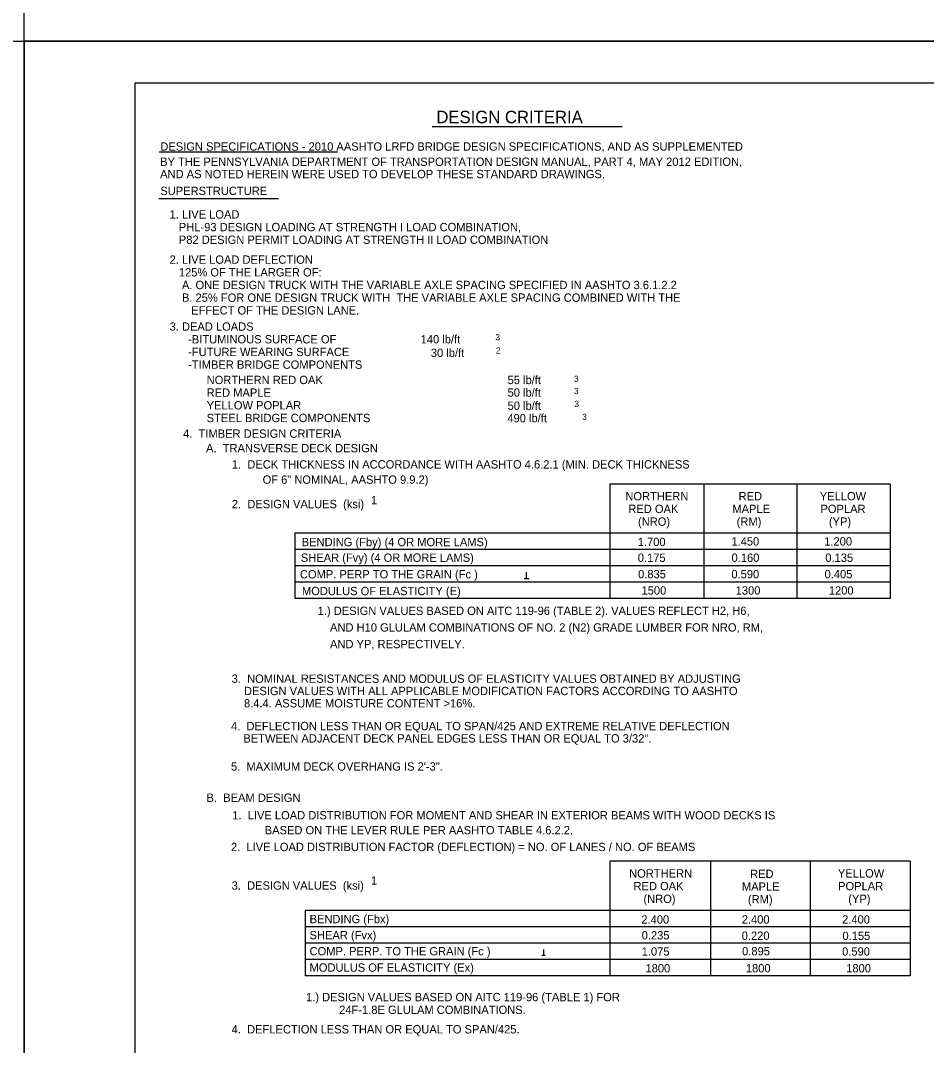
# Model space of a CAD drawing. Extents: x 637594 to 640253, y 297247 to 298435.
# Drawn here: x 639275.1 to 639602, y 297479.2 to 297849 of the extents above; entities that cross this region are included whole.
import ezdxf

# ---------------------------------------------------------------- set-up
doc = ezdxf.new("R2010")
doc.units = 0
for name, color, linetype in [('2', 7, 'Continuous'), ('53', 7, 'Continuous'), ('Level 2', 7, 'Continuous'), ('Level 53', 7, 'Continuous'), ('PLT-BNDY', 7, 'Continuous')]:
    doc.layers.add(name, color=color, linetype=linetype)

msp = doc.modelspace()

# ---------------------------------------------------------------- linework, layer by layer
at = {"layer": '2'}
for p, q in [((639316.46, 297262.46), (639316.46, 297826.46)), ((639316.46, 297826.46), (640102.46, 297826.46))]:
    msp.add_line(p, q, dxfattribs=at)
at = {"layer": '53'}
msp.add_line((639423.58, 297810.75), (639492.23, 297810.75), dxfattribs=at)
at = {"layer": 'Level 2'}
for p, q in [((639588.92, 297681.72), (639487.78, 297681.72)), ((639487.78, 297681.72), (639487.78, 297640.41)), ((639521.66, 297681.72), (639521.66, 297640.41)), ((639555.26, 297681.72), (639555.26, 297640.41)), ((639588.92, 297681.72), (639588.92, 297640.41)), ((639374.08, 297664.01), (639374.08, 297640.41)), ((639487.78, 297664.01), (639374.08, 297664.01)), ((639588.92, 297664.01), (639487.78, 297664.01)), ((639487.78, 297658.11), (639374.08, 297658.11)), ((639588.92, 297658.11), (639487.78, 297658.11)), ((639487.78, 297652.21), (639374.08, 297652.21)), ((639588.92, 297652.21), (639487.78, 297652.21)), ((639457.65, 297647.72), (639457.65, 297649.98)), ((639487.78, 297646.31), (639374.08, 297646.31)), ((639456.83, 297647.72), (639458.48, 297647.72)), ((639588.92, 297646.31), (639487.78, 297646.31)), ((639487.78, 297640.41), (639374.08, 297640.41)), ((639588.92, 297640.41), (639487.78, 297640.41)), ((639596.16, 297545.65), (639487.78, 297545.65)), ((639487.78, 297545.65), (639487.78, 297504.34)), ((639524.02, 297545.65), (639524.02, 297504.34)), ((639560.02, 297545.65), (639560.02, 297504.34)), ((639596.16, 297545.65), (639596.16, 297504.34)), ((639377.82, 297527.95), (639377.82, 297504.34)), ((639487.78, 297527.95), (639377.83, 297527.95)), ((639596.16, 297527.95), (639487.78, 297527.95)), ((639487.78, 297522.05), (639377.83, 297522.05)), ((639596.16, 297522.05), (639487.78, 297522.05)), ((639487.78, 297516.15), (639377.83, 297516.15)), ((639596.16, 297516.15), (639487.78, 297516.15)), ((639463.2, 297511.75), (639464.42, 297511.75)), ((639463.8, 297513.79), (639463.8, 297511.75)), ((639487.78, 297510.24), (639377.83, 297510.24)), ((639596.16, 297510.24), (639487.78, 297510.24)), ((639487.78, 297504.34), (639377.83, 297504.34)), ((639596.16, 297504.34), (639487.78, 297504.34))]:
    msp.add_line(p, q, dxfattribs=at)
at = {"layer": 'Level 53'}
for p, q in [((639325.13, 297801.6), (639389.52, 297801.6)), ((639325.04, 297784.77), (639368.14, 297784.77))]:
    msp.add_line(p, q, dxfattribs=at)
at = {"layer": 'PLT-BNDY'}
for points in [[(639276.46, 298435.46), (640117.46, 298435.46), (640117.46, 297841.46), (639276.46, 297841.46)], [(638435.46, 297841.46), (639276.46, 297841.46), (639276.46, 297247.46), (638435.46, 297247.46)], [(639276.46, 297841.46), (640117.46, 297841.46), (640117.46, 297247.46), (639276.46, 297247.46)]]:
    msp.add_lwpolyline(points, close=True, dxfattribs=at)

# ---------------------------------------------------------------- texts
at = {"layer": '2'}
for s, p in [('3', (639446.45, 297733.56)), ('2', (639446.68, 297728.81)), ('3', (639474.79, 297718.6)), ('3', (639474.79, 297714.17)), ('3', (639474.95, 297709.52)), ('3', (639477.77, 297704.86))]:
    msp.add_text(s, height=2.25, dxfattribs=at).set_placement(p)
at = {"layer": '53'}
msp.add_text('DESIGN CRITERIA', height=4.5002, dxfattribs=at).set_placement((639425.15, 297811.9))
at = {"layer": 'Level 2'}
for s, p in [('55 lb/ft ', (639450.85, 297717.79)), ('50 lb/ft ', (639450.85, 297713.26)), ('50 lb/ft ', (639450.85, 297708.5)), ('490 lb/ft ', (639450.77, 297704.02)), ('4.  TIMBER DESIGN CRITERIA', (639333.78, 297698.43)), ('A.  TRANSVERSE DECK DESIGN', (639342.05, 297693.2)), ('1.  DECK THICKNESS IN ACCORDANCE WITH AASHTO 4.6.2.1 (MIN. DECK THICKNESS', (639351.37, 297687.34)), ('OF 6" NOMINAL, AASHTO 9.9.2)', (639362.46, 297681.84)), ('1', (639401.58, 297674.48)), ('NORTHERN', (639493.34, 297675.86)), ('RED', (639534.19, 297675.86)), ('YELLOW', (639563.49, 297675.86)), ('2.  DESIGN VALUES  (ksi)', (639351.37, 297673.03)), ('RED OAK', (639494.41, 297671.28)), ('MAPLE', (639531.95, 297671.28)), ('POPLAR', (639563.73, 297671.28)), ('(NRO)', (639497.9, 297666.69)), ('(RM)', (639533.51, 297666.69)), ('(YP)', (639566.78, 297666.69)), ('1.450', (639531.6, 297659.57)), ('1.200', (639565.09, 297659.57)), ('BENDING (Fby) (4 OR MORE LAMS)', (639376.57, 297659.33)), ('1.700', (639497.81, 297659.37)), ('SHEAR (Fvy) (4 OR MORE LAMS)', (639376.26, 297653.68)), ('0.175', (639497.82, 297653.66)), ('0.160', (639531.66, 297653.66)), ('0.135', (639565.49, 297653.66)), ('COMP. PERP TO THE GRAIN (Fc )', (639375.92, 297647.7)), ('0.835', (639497.94, 297647.76)), ('0.590', (639531.6, 297647.76)), ('0.405', (639565.22, 297647.76)), ('MODULUS OF ELASTICITY (E)', (639376.65, 297641.66)), ('1500', (639499.18, 297641.86)), ('1300', (639533.15, 297641.86)), ('1200', (639566.76, 297641.86)), ('1.) DESIGN VALUES BASED ON AITC 119-96 (TABLE 2). VALUES REFLECT H2, H6,', (639382.32, 297634.52)), ('    AND H10 GLULAM COMBINATIONS OF NO. 2 (N2) GRADE LUMBER FOR NRO, RM,', (639382.32, 297628.52)), ('    AND YP, RESPECTIVELY.', (639382.32, 297622.52)), ('3.  NOMINAL RESISTANCES AND MODULUS OF ELASTICITY VALUES OBTAINED BY ADJUSTING', (639351.28, 297610.04)), ('    DESIGN VALUES WITH ALL APPLICABLE MODIFICATION FACTORS ACCORDING TO AASHTO', (639351.28, 297605.6)), ('    8.4.4. ASSUME MOISTURE CONTENT >16%. ', (639351.28, 297601.16)), ('4.  DEFLECTION LESS THAN OR EQUAL TO SPAN/425 AND EXTREME RELATIVE DEFLECTION', (639351.06, 297592.94)), ('    BETWEEN ADJACENT DECK PANEL EDGES LESS THAN OR EQUAL TO 3/32".', (639351.06, 297588.5)), ('5.  MAXIMUM DECK OVERHANG IS 2\'-3".', (639351.06, 297578.37)), ('B.  BEAM DESIGN', (639342.22, 297567.1)), ('1.  LIVE LOAD DISTRIBUTION FOR MOMENT AND SHEAR IN EXTERIOR BEAMS WITH WOOD DECKS IS', (639351.51, 297560.77)), ('BASED ON THE LEVER RULE PER AASHTO TABLE 4.6.2.2.', (639363.23, 297555.39)), ('2.  LIVE LOAD DISTRIBUTION FACTOR (DEFLECTION) = NO. OF LANES / NO. OF BEAMS', (639351.06, 297549.34)), ('NORTHERN', (639494.7, 297539.8)), ('RED', (639538.35, 297539.62)), ('YELLOW', (639570.03, 297539.8)), ('3.  DESIGN VALUES  (ksi)', (639351.28, 297535.42)), ('1', (639401.58, 297537.26)), ('RED OAK', (639496.27, 297535.21)), ('MAPLE', (639535.39, 297535.04)), ('POPLAR', (639570.1, 297535.21)), ('(NRO)', (639499.86, 297530.62)), ('(RM)', (639537.56, 297530.45)), ('(YP)', (639573.77, 297530.62)), ('BENDING (Fbx)', (639379.4, 297523.34)), ('2.400', (639499.11, 297523.18)), ('2.400', (639535.33, 297523.18)), ('2.400', (639571.54, 297523.18)), ('SHEAR (Fvx)', (639379.4, 297517.53)), ('0.235', (639499.24, 297517.47)), ('0.220', (639535.33, 297517.32)), ('0.155', (639571.67, 297517.28)), ('COMP. PERP. TO THE GRAIN (Fc )', (639379.4, 297511.73)), ('0.895', (639535.46, 297511.74)), ('1.075', (639499.24, 297511.63)), ('0.590', (639571.54, 297511.64)), ('MODULUS OF ELASTICITY (Ex)', (639379.4, 297505.83)), ('1800', (639500.6, 297505.59)), ('1800', (639536.82, 297505.59)), ('1800', (639573.03, 297505.59)), ('1.) DESIGN VALUES BASED ON AITC 119-96 (TABLE 1) FOR', (639378.11, 297495.18)), ('24F-1.8E GLULAM COMBINATIONS.', (639390.08, 297490.59)), ('4.  DEFLECTION LESS THAN OR EQUAL TO SPAN/425.', (639351.28, 297483.56))]:
    msp.add_text(s, height=3, dxfattribs=at).set_placement(p)
at = {"layer": 'Level 53'}
for s, p in [('DESIGN SPECIFICATIONS - 2010 AASHTO LRFD BRIDGE DESIGN SPECIFICATIONS, AND AS SUPPLEMENTED', (639325.55, 297802)), ('BY THE PENNSYLVANIA DEPARTMENT OF TRANSPORTATION DESIGN MANUAL, PART 4, MAY 2012 EDITION,', (639325.49, 297796.51)), ('AND AS NOTED HEREIN WERE USED TO DEVELOP THESE STANDARD DRAWINGS.', (639325.49, 297792.07)), ('SUPERSTRUCTURE', (639325.55, 297786.01)), ('   1. LIVE LOAD', (639325.55, 297777.52)), ('      PHL-93 DESIGN LOADING AT STRENGTH I LOAD COMBINATION,', (639325.55, 297772.94)), ('      P82 DESIGN PERMIT LOADING AT STRENGTH II LOAD COMBINATION', (639325.55, 297768.37)), ('   2. LIVE LOAD DEFLECTION', (639325.55, 297761.2)), ('      125% OF THE LARGER OF:', (639325.55, 297756.63)), ('       A. ONE DESIGN TRUCK WITH THE VARIABLE AXLE SPACING SPECIFIED IN AASHTO 3.6.1.2.2', (639325.55, 297752.05)), ('       B. 25% FOR ONE DESIGN TRUCK WITH  THE VARIABLE AXLE SPACING COMBINED WITH THE ', (639325.55, 297747.48)), ('          EFFECT OF THE DESIGN LANE.', (639325.55, 297742.9)), ('   3. DEAD LOADS', (639325.55, 297737.05)), ('         -BITUMINOUS SURFACE OF ', (639325.55, 297732.47)), ('140 lb/ft ', (639419.49, 297732.47)), ('         -FUTURE WEARING SURFACE ', (639325.55, 297727.9)), ('30 lb/ft ', (639423.16, 297727.58)), ('         -TIMBER BRIDGE COMPONENTS', (639325.55, 297723.32)), ('               NORTHERN RED OAK', (639325.55, 297717.8)), ('               RED MAPLE', (639325.55, 297713.23)), ('               YELLOW POPLAR', (639325.55, 297708.65)), ('               STEEL BRIDGE COMPONENTS', (639325.55, 297704.08))]:
    msp.add_text(s, height=3, dxfattribs=at).set_placement(p)

doc.saveas('drawing.dxf')
